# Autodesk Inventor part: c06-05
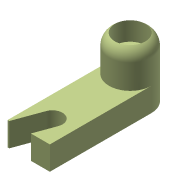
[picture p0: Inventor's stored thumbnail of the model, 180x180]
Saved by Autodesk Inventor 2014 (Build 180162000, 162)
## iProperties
Created: 2013-03
Part Number: c06-05
Material: Aluminum 6061
Document SubType Name: Modeling
Designer: Thom Tremblay
Density: 2.71 g/cm^3
Appearance: Zinc Chromate 2
Author: Thom Tremblay
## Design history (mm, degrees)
sketch "Sketch1"
  geometry: L1 (0, -12.5)-(60, -12.5); L2 (60, -12.5)-(60, 12.5); L3 (60, 12.5)-(0, 12.5); L4 (0, 12.5)-(0, -12.5); 2 further points
  constraints: 8 end point, 2 parallel, 1 coincident, 1 horizontal, 1 midpoint, 1 perpendicular
  dimensions: "d1" = 25 distance of L2.end L1.end; "d2" = 60 distance of L2.end L3.end
extrude "Base" new body sketch "Sketch1" distance "d3" = 14; taper "d4" = 0 deg
sketch "Sketch2"
  geometry: C1 r 12.5 at (0, 0); 1 further point
  constraints: 1 centre point, 1 coincident
extrude "Boss" join sketch "Sketch2" distance "d5" = 35; taper "d6" = 0 deg
sketch "Sketch3"
  geometry: L1 (-60, 12.5)-(-60, -12.5) reference; L2 (-60, -6)-(-60, 6); L3 (-43.948, 5.638)-(-60, 11.481); L4 (-48.052, -5.638)-(-60, -1.289); L5 (-60, 11.481)-(-60, -1.289); A1 r 6 centre (-46, 0) between (-43.948, 5.638) and (-48.052, -5.638); 2 further points
  constraints: 8 end point, 3 midpoint, 2 point on circle, 2 point on line, 2 tangent, 1 centre point, 1 collinear, 1 horizontal alignment, 1 parallel
  dimensions: "d8" = 12 diameter of A1; "d20" = 20 dimension on A1 L1; "d27" = 70 deg angle of L1 L3
extrude "Slot" cut sketch "Sketch3" stored distance "d9" = 24; taper "d10" = 0 deg
hole "Hole1" diameter "d13" = 11; stored, may be unused: countersink angle "d17" = 90 deg, drill point angle "d19" = 118 deg; dims "d11" = 10, "d12" = 10, "d14" = 6, "d15" = 18, "d16" = 11, "d18" = 8
fillet "Fillet1" dims "d26" = 8
node "Midplane between faces"
node "Normal to Edge at Point"
body "Solid1"
